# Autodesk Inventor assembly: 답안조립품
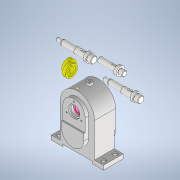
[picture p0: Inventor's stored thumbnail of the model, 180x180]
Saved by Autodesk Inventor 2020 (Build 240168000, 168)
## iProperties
Created: 2021-05
Part Number: 답안조립품
Document SubType Name: Assembly
Designer: Owner
Author: Owner
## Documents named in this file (11)
- C:\Users\Owner\Desktop\710507V1014\답안조립품.iam
- C:\Users\Owner\Desktop\710507V1014\본체.ipt
- C:\Users\Owner\Desktop\710507V1014\베어링 6002.ipt
- 베어링 6002.ipt
- C:\Users\Owner\Desktop\710507V1014\베어링 6001.ipt
- 베어링 6001.ipt
- C:\Users\Owner\Desktop\710507V1014\축 A.ipt
- C:\Users\Owner\Desktop\710507V1014\스퍼기어 A.ipt
- C:\Users\Owner\Desktop\710507V1014\스퍼기어 B.ipt
- C:\Users\Owner\Desktop\710507V1014\축 B.ipt
- C:\Users\Owner\Desktop\710507V1014\키 4 x 4 x 12.ipt
